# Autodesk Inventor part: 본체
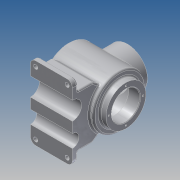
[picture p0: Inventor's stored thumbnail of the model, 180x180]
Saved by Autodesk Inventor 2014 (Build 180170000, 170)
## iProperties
Created: 2018-08
Part Number: 본체
Material: 알루미늄 6061
Document SubType Name: Modeling
Designer: kb542
Density: 2.71 g/cm^3
Appearance: 알루미늄 - 평지
Mass: 1886.05 g
Surface Area: 1087.48 cm^2
Volume: 695.96 cm^3
Author: kb542
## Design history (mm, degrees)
sketch "스케치1"
  geometry: L1 (0, 0)-(-120, 0); L2 (-120, 0)-(-120, 38); L3 (-120, 38)-(-108, 38); L4 (-108, 38)-(-108, 50); L5 (-108, 50)-(-11.329, 50); L6 (-17.837, 40)-(-98, 40); L7 (-98, 40)-(-98, 27); L8 (-98, 27)-(-120, 27); A1 r 116 centre (-116, 0) between (0, 0) and (-11.329, 50); A2 r 106 centre (-116, 0) between (-10, 0) and (-17.837, 40)
  constraints: 16 end point, 4 point on circle, 3 parallel, 3 point on line, 2 centre point, 2 perpendicular, 1 horizontal, 1 other
  dimensions: "d0" = 116 radius of A1; "d2" = 12 distance of L2.end L3.end; "d3" = 108 horizontal distance of L1.start L4.end; "d4" = 76 diameter of L3 L1; "d5" = 100 diameter of L5 L1; "d7" = 80 diameter of L6 L1; "d8" = 54 diameter of L8 L1; "d9" = 10 radial gap between concentric circles of A1 A2
revolve "회전1" sketch "스케치1" stored, may be unused: angle "d10" = 90 deg
node "작업 평면1"
sketch "스케치2"
  geometry: L1 (0, -50)-(0, -82); L2 (0, -82)-(-70, -82); L3 (-70, -82)-(-70, -72); L4 (-70, -72)-(-50, -72); L5 (-50, -72)-(-50, -43.437); L6 (-70, -72)-(-40.304, -29.59); L7 (70, -72)-(40.304, -29.59); L8 (50, -72)-(50, -43.437); L9 (70, -72)-(50, -72); L10 (70, -82)-(70, -72); L11 (0, -82)-(70, -82); A1 r 50 centre (0, 0) between (0, -50) and (-40.304, -29.59) reference; A2 r 12.5 centre (-27.5, -82) between (-15, -82) and (-40, -82); A3 r 17.5 centre (22.5, -82) between (40, -82) and (5, -82); 1 further point
  constraints: 22 end point, 8 point on line, 6 point on circle, 5 symmetric about line, 3 parallel, 2 centre point, 2 perpendicular, 1 vertical, 1 vertical alignment
  dimensions: "d12" = 82 distance from line of L2 point (0, 0); "d13" = 20 distance of L3.end L4.end; "d15" = 140 diameter of L3 L1; "d18" = 10 distance of L2.end L3.end; "d19" = 35 deg angle of L6 L3; "d20" = 12.5 radius of A2; "d21" = 17.5 radius of A3; "d22" = 27.5 distance of L1.end A2.centre; "d24" = 22.5 distance of A3.centre L1.end
extrude "돌출1" join sketch "스케치2" distance "d25" = 80; taper "d26" = 0 deg
sketch "스케치3"
  geometry: L1 (-70, -82)-(70, -82) reference; C1 r 17.5 at (-22.5, -82); C2 r 12.5 at (27.5, -82); A1 r 50 centre (0, 0) between (-40.304, -29.59) and (40.304, -29.59) reference
  constraints: 2 centre point, 2 point on line
  dimensions: "d27" = 22.5 horizontal distance of A1.centre C1.centre; "d28" = 27.5 horizontal distance of C2.centre A1.centre; "d29" = 17.5 radius of C1; "d30" = 12.5 radius of C2
extrude "돌출2" cut sketch "스케치3" stored distance "d31" = 80; taper "d32" = 0 deg
node "작업 평면2"
sketch "스케치4"
  geometry: L1 (-88, -120)-(-88, -20) reference; C1 r 38 at (-38, -70); 2 further points
  constraints: 1 centre point, 1 horizontal alignment, 1 midpoint
  dimensions: "d34" = 50 distance from line of C1.centre L1; "d35" = 76 diameter of C1
extrude "돌출3" join sketch "스케치4" stored distance "d36" = 80; taper "d37" = 0 deg
sketch "스케치5"
  geometry: C1 r 38 at (0, 0) reference; C2 r 27 at (0, 0); 1 further point
  constraints: 1 centre point, 1 coincident
  dimensions: "d38" = 54 diameter of C2
extrude "돌출4" cut sketch "스케치5" stored distance "d39" = 80; taper "d40" = 0 deg
sketch "스케치6"
  geometry: C1 r 27 at (0, 0) reference; 2 further points
  constraints: 1 vertical alignment
  dimensions: "d41" = 32.5 distance of C1.centre point (0, 32.5)
hole "구멍1" sketch "스케치6" at (0, 32.5) diameter "d42" = 3.242; stored, may be unused: countersink angle "d46" = 90 deg, drill point angle "d48" = 118 deg; dims "d43" = 8, "d44" = 4, "d45" = 2, "d47" = 10
sketch "스케치7"
  geometry: C1 r 27 at (0, 0) reference; 1 further point
  constraints: 1 vertical alignment
  dimensions: "d52" = 32.5 distance of C1.centre point (0, 32.5)
hole "구멍2" sketch "스케치7" at (0, 32.5) diameter "d53" = 3.242; stored, may be unused: countersink angle "d57" = 90 deg, drill point angle "d59" = 118 deg; dims "d54" = 8, "d55" = 4, "d56" = 2, "d58" = 10
fillet "모깎기1" dims "d63" = 10
sketch "스케치8"
  geometry: L1 (0, 110)-(0, 100) reference; L2 (80, 100)-(0, 100) reference; L3 (80, 100)-(80, 110) reference; L4 (70, 120)-(10, 120) reference; A1 r 10 centre (10, -10) between (0, -10) and (10, -20) reference; A2 r 10 centre (70, -10) between (70, -20) and (80, -10) reference; A3 r 10 centre (10, 110) between (10, 120) and (0, 110) reference; A4 r 10 centre (70, 110) between (80, 110) and (70, 120) reference; 5 further points
  constraints: 4 coincident
hole "구멍3" sketch "스케치8" at (10, 110), (70, 110), (70, -10), (10, -10) diameter "d64" = 8; stored, may be unused: countersink angle "d68" = 90 deg, drill point angle "d70" = 118 deg; dims "d65" = 8, "d66" = 4, "d67" = 2, "d69" = 10
fillet "모깎기2" dims "d71" = 3
chamfer "모따기1" distance "d72" = 1; stored, may be unused: second distance "d73" = 2, angle "d74" = 45 deg
fillet "모깎기3" dims "d75" = 3
node "작업 평면3"
sketch "스케치9"
  geometry: C1 r 32.5 at (0, 0); 1 further point
  constraints: 1 centre point, 1 coincident, 1 other
  dimensions: "d76" = 65 diameter of C1
feature "엠보싱1" sketch "스케치9" dims "d0" = 116, "d2" = 12, "d3" = 108, "d4" = 76, "d5" = 100, "d7" = 80, "d8" = 54, "d9" = 10, "d12" = 82, "d13" = 20, "d15" = 140, "d18" = 10, "d19" = 35 deg, "d20" = 12.5, "d21" = 17.5, "d22" = 27.5, "d24" = 22.5, "d77" = 0.5, "d78" = 0
node "솔리드1"
mirror "대칭1"
pattern_circular "원형 패턴1" dims angle "d50" = 360 deg
pattern_circular "원형 패턴2" dims angle "d61" = 360 deg
node "투영된 루프1"
other parameters: "d11" = -8, "d33" = -147
